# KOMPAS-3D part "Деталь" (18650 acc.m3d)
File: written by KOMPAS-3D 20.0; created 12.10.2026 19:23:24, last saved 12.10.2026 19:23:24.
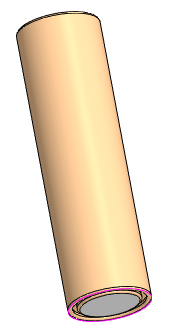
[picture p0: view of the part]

Document properties: Полное имя файла: D:\myProjects\Progect_esp32\box_compas\18650 acc.m3d

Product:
- Part/product: Деталь
    Масса: 0.12809

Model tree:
1. Эскиз:1
2. Элемент выдавливания:1
     Расстояние 1 = 65
3. Эскиз:2  (with: Элемент выдавливания:1)
4. Элемент выдавливания:2
     Расстояние 2 = 1
5. Эскиз:3  (with: Элемент выдавливания:1)
6. Элемент выдавливания:3
     Расстояние 2 = 1
7. Скругление:1  (with: Элемент выдавливания:3, Элемент выдавливания:1, Элемент выдавливания:2)
     Радиус = 0.5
